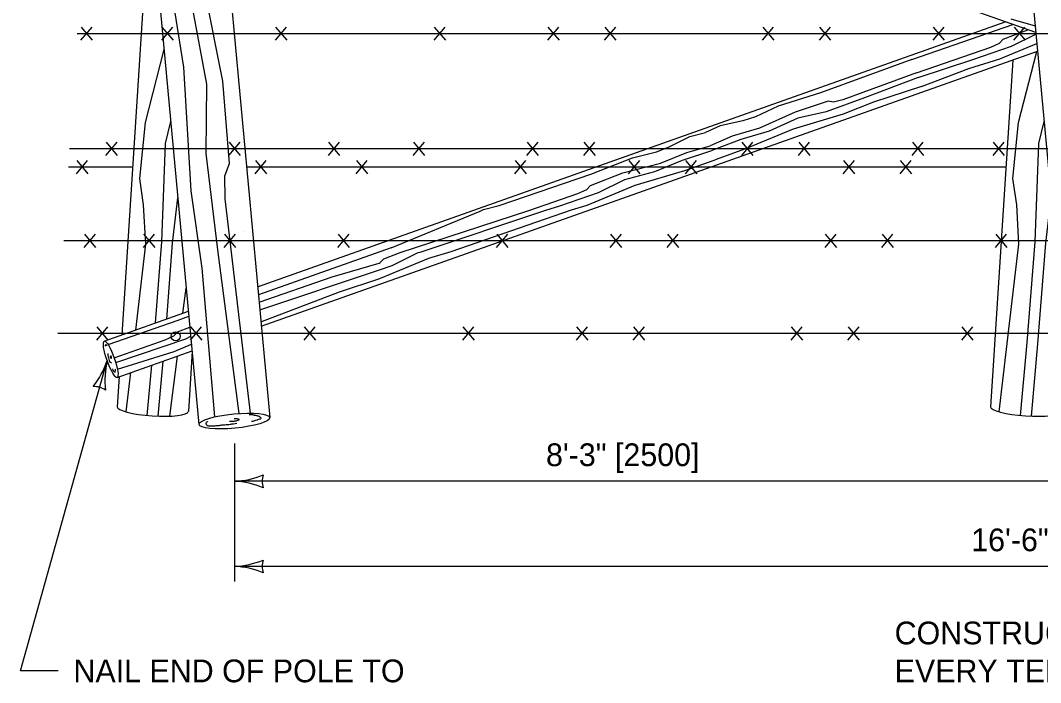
# Model space of a CAD drawing. Extents: x 49991.4 to 50021, y 49987.6 to 50011.4.
# Drawn here: x 50009.373 to 50012.065, y 49990.289 to 49992.035 of the extents above; entities that cross this region are included whole.
import ezdxf

# ---------------------------------------------------------------- set-up
doc = ezdxf.new("R2010")
doc.units = 0
for name, color, linetype in [('Level 1', 7, 'Continuous'), ('Level 2', 7, 'Continuous'), ('Level 3', 7, 'Continuous')]:
    doc.layers.add(name, color=color, linetype=linetype)

msp = doc.modelspace()

# ---------------------------------------------------------------- linework, layer by layer
at = {"layer": 'Level 1'}
for p, q in [((50009.7558, 49992.9922), (50009.6409, 49991.206)), ((50012.0526, 49992.0031), (50010.2289, 49992.649)), ((50009.9017, 49992.3783), (50010.0312, 49990.9877)), ((50009.7178, 49992.3281), (50009.8443, 49990.9698)), ((50012.0223, 49992.3281), (50012.1488, 49990.9698)), ((50009.9991, 49991.3328), (50011.9723, 49992.0316)), ((50011.987, 49992.0392), (50012.0509, 49992.0211)), ((50009.5224, 49992.001), (50010.3579, 49992.001)), ((50009.5327, 49991.9829), (50009.562, 49992.0176)), ((50009.5634, 49991.9829), (50009.534, 49992.0176)), ((50009.746, 49991.9829), (50009.7754, 49992.0176)), ((50009.7767, 49991.9829), (50009.7474, 49992.0176)), ((50010.046, 49991.9829), (50010.0754, 49992.0176)), ((50010.0767, 49991.9829), (50010.0474, 49992.0176)), ((50010.3579, 49992.001), (50012.6067, 49992.001)), ((50010.4648, 49991.9829), (50010.4942, 49992.0176)), ((50010.4955, 49991.9829), (50010.4662, 49992.0176)), ((50010.7648, 49991.9829), (50010.7942, 49992.0176)), ((50010.7955, 49991.9829), (50010.7662, 49992.0176)), ((50010.9148, 49991.9829), (50010.9442, 49992.0176)), ((50010.9455, 49991.9829), (50010.9162, 49992.0176)), ((50011.3315, 49991.9829), (50011.3608, 49992.0176)), ((50011.3622, 49991.9829), (50011.3328, 49992.0176)), ((50011.4815, 49991.9829), (50011.5108, 49992.0176)), ((50011.5122, 49991.9829), (50011.4828, 49992.0176)), ((50011.7815, 49991.9829), (50011.8108, 49992.0176)), ((50011.8122, 49991.9829), (50011.7828, 49992.0176)), ((50011.9948, 49991.9829), (50012.0242, 49992.0176)), ((50012.0255, 49991.9829), (50011.9962, 49992.0176)), ((50010.878, 49991.5364), (50012.0572, 49991.9539)), ((50011.9921, 49991.9309), (50011.9332, 49991.0165)), ((50009.5987, 49991.6795), (50009.6281, 49991.7142)), ((50009.6294, 49991.6795), (50009.6001, 49991.7142)), ((50009.9232, 49991.6795), (50009.9526, 49991.7142)), ((50009.9539, 49991.6795), (50009.9246, 49991.7142)), ((50010.1857, 49991.6795), (50010.2151, 49991.7142)), ((50010.2164, 49991.6795), (50010.1871, 49991.7142)), ((50010.4098, 49991.6795), (50010.4392, 49991.7142)), ((50010.4405, 49991.6795), (50010.4112, 49991.7142)), ((50010.7098, 49991.6795), (50010.7392, 49991.7142)), ((50010.7405, 49991.6795), (50010.7112, 49991.7142)), ((50010.8598, 49991.6795), (50010.8892, 49991.7142)), ((50010.8905, 49991.6795), (50010.8612, 49991.7142)), ((50011.2765, 49991.6795), (50011.3058, 49991.7142)), ((50011.3072, 49991.6795), (50011.2778, 49991.7142)), ((50011.4265, 49991.6795), (50011.4558, 49991.7142)), ((50011.4572, 49991.6795), (50011.4278, 49991.7142)), ((50011.7265, 49991.6795), (50011.7558, 49991.7142)), ((50011.7572, 49991.6795), (50011.7278, 49991.7142)), ((50011.9398, 49991.6795), (50011.9692, 49991.7142)), ((50011.9705, 49991.6795), (50011.9412, 49991.7142)), ((50009.5028, 49991.6976), (50010.3029, 49991.6976)), ((50010.3029, 49991.6976), (50012.5517, 49991.6976)), ((50009.4997, 49991.6491), (50009.6701, 49991.6491)), ((50009.5211, 49991.631), (50009.5504, 49991.6657)), ((50009.5518, 49991.631), (50009.5224, 49991.6657)), ((50009.9686, 49991.6491), (50011.9739, 49991.6491)), ((50009.9925, 49991.631), (50010.0219, 49991.6657)), ((50010.0232, 49991.631), (50009.9939, 49991.6657)), ((50010.2591, 49991.631), (50010.2885, 49991.6657)), ((50010.2898, 49991.631), (50010.2605, 49991.6657)), ((50010.6779, 49991.631), (50010.7073, 49991.6657)), ((50010.7086, 49991.631), (50010.6793, 49991.6657)), ((50010.9779, 49991.631), (50011.0073, 49991.6657)), ((50011.0086, 49991.631), (50010.9793, 49991.6657)), ((50011.1279, 49991.631), (50011.1573, 49991.6657)), ((50011.1586, 49991.631), (50011.1293, 49991.6657)), ((50011.5446, 49991.631), (50011.5739, 49991.6657)), ((50011.5753, 49991.631), (50011.5459, 49991.6657)), ((50011.6946, 49991.631), (50011.7239, 49991.6657)), ((50011.7253, 49991.631), (50011.6959, 49991.6657)), ((50010.0088, 49991.2286), (50010.878, 49991.5364)), ((50010.3512, 49991.4356), (50010.586, 49991.5321)), ((50010.3755, 49991.4235), (50010.7145, 49991.534)), ((50010.4284, 49991.4243), (50010.76, 49991.5347)), ((50010.51, 49991.4256), (50010.8277, 49991.5356)), ((50009.5416, 49991.4368), (50009.5709, 49991.4715)), ((50009.5723, 49991.4368), (50009.5429, 49991.4715)), ((50009.6977, 49991.4368), (50009.727, 49991.4715)), ((50009.7284, 49991.4368), (50009.699, 49991.4715)), ((50009.911, 49991.4368), (50009.9404, 49991.4715)), ((50009.9417, 49991.4368), (50009.9124, 49991.4715)), ((50009.9655, 49991.4793), (50009.9655, 49991.4793)), ((50010.211, 49991.4368), (50010.2404, 49991.4715)), ((50010.2417, 49991.4368), (50010.2124, 49991.4715)), ((50010.6298, 49991.4368), (50010.6592, 49991.4715)), ((50010.6605, 49991.4368), (50010.6312, 49991.4715)), ((50010.9298, 49991.4368), (50010.9592, 49991.4715)), ((50010.9605, 49991.4368), (50010.9312, 49991.4715)), ((50011.0798, 49991.4368), (50011.1092, 49991.4715)), ((50011.1105, 49991.4368), (50011.0812, 49991.4715)), ((50011.4965, 49991.4368), (50011.5258, 49991.4715)), ((50011.5272, 49991.4368), (50011.4978, 49991.4715)), ((50011.6465, 49991.4368), (50011.6758, 49991.4715)), ((50011.6772, 49991.4368), (50011.6478, 49991.4715)), ((50011.9465, 49991.4368), (50011.9758, 49991.4715)), ((50011.9772, 49991.4368), (50011.9478, 49991.4715)), ((50009.4872, 49991.4549), (50010.5229, 49991.4549)), ((50010.3512, 49991.4356), (50010.0011, 49991.3118)), ((50010.5229, 49991.4549), (50012.7717, 49991.4549)), ((50010.196, 49991.3591), (50010.3195, 49991.3951)), ((50010.0029, 49991.2919), (50010.196, 49991.3591)), ((50010.0048, 49991.2717), (50010.3211, 49991.3773)), ((50010.2151, 49991.3196), (50010.3213, 49991.3547)), ((50009.5943, 49991.1895), (50009.8165, 49991.2682)), ((50009.5743, 49991.1923), (50009.6036, 49991.227)), ((50009.605, 49991.1923), (50009.5756, 49991.227)), ((50009.8216, 49991.1923), (50009.851, 49991.227)), ((50009.8523, 49991.1923), (50009.823, 49991.227)), ((50010.1216, 49991.1923), (50010.151, 49991.227)), ((50010.1523, 49991.1923), (50010.123, 49991.227)), ((50010.5404, 49991.1923), (50010.5698, 49991.227)), ((50010.5711, 49991.1923), (50010.5418, 49991.227)), ((50010.8404, 49991.1923), (50010.8698, 49991.227)), ((50010.8711, 49991.1923), (50010.8418, 49991.227)), ((50010.9904, 49991.1923), (50011.0198, 49991.227)), ((50011.0211, 49991.1923), (50010.9918, 49991.227)), ((50011.4071, 49991.1923), (50011.4364, 49991.227)), ((50011.4378, 49991.1923), (50011.4084, 49991.227)), ((50011.5571, 49991.1923), (50011.5864, 49991.227)), ((50011.5878, 49991.1923), (50011.5584, 49991.227)), ((50011.8571, 49991.1923), (50011.8864, 49991.227)), ((50011.8878, 49991.1923), (50011.8584, 49991.227)), ((50009.4715, 49991.2105), (50010.4335, 49991.2105)), ((50010.4335, 49991.2105), (50012.6823, 49991.2105)), ((50009.6285, 49991.0939), (50009.8262, 49991.1639)), ((50009.8263, 49991.1628), (50009.8163, 49991.0042)), ((50009.6338, 49991.0958), (50009.6287, 49991.0165))]:
    msp.add_line(p, q, dxfattribs=at)
for points in [[(50009.9505, 49990.9988), (50009.8938, 49991.4307), (50009.8632, 49991.6848), (50009.8653, 49991.8677), (50009.8285, 49992.0604), (50009.8176, 49992.2455), (50009.8033, 49992.3553)], [(50009.9799, 49990.9996), (50009.913, 49991.5649), (50009.9125, 49991.6258), (50009.9245, 49991.6576), (50009.9071, 49991.8755), (50009.8594, 49992.1145), (50009.8493, 49992.2929), (50009.8373, 49992.3594)], [(50009.8863, 49990.9899), (50009.853, 49991.3822), (50009.8235, 49991.5856), (50009.8047, 49991.9121), (50009.7533, 49992.2317), (50009.7412, 49992.3433)], [(50011.7257, 49991.9327), (50011.9925, 49992.0244)], [(50011.7382, 49991.8973), (50011.9339, 49991.9645), (50011.9572, 49991.9754), (50011.967, 49991.9857), (50012.0314, 49992.0106)], [(50011.7425, 49991.8852), (50011.8866, 49991.9327), (50011.9885, 49991.9675), (50012.0529, 49991.9993)], [(50011.7511, 49991.8609), (50011.8756, 49991.9084), (50011.9582, 49991.9343), (50012.0553, 49991.9743)], [(50009.6772, 49991.2188), (50009.7037, 49991.4452), (50009.6982, 49991.5488), (50009.6879, 49991.6186), (50009.703, 49991.7661), (50009.7522, 49991.9589)], [(50011.9564, 49991.0028), (50011.9855, 49991.2512), (50012.0083, 49991.4452), (50012.0028, 49991.5488), (50011.9925, 49991.6186), (50012.0075, 49991.7661), (50012.0553, 49991.9533)], [(50011.7257, 49991.9327), (50011.4846, 49991.8448), (50011.3725, 49991.8091), (50011.3132, 49991.7814), (50011.2794, 49991.7708), (50011.2193, 49991.7577), (50011.1809, 49991.7398)], [(50011.7382, 49991.8973), (50011.5438, 49991.8263), (50011.519, 49991.8202), (50011.5048, 49991.822), (50011.4173, 49991.7938), (50011.3239, 49991.7511), (50011.2518, 49991.7297), (50011.1934, 49991.7043)], [(50011.7425, 49991.8852), (50011.6007, 49991.8314), (50011.4995, 49991.7943), (50011.4245, 49991.7775), (50011.3491, 49991.7437), (50011.2743, 49991.7213), (50011.1977, 49991.6922)], [(50011.7511, 49991.8609), (50011.6245, 49991.8194), (50011.544, 49991.7877), (50011.4121, 49991.7483), (50011.2862, 49991.6964), (50011.2063, 49991.668)], [(50009.7295, 49991.2374), (50009.7464, 49991.451), (50009.7563, 49991.711), (50009.7699, 49991.7691)], [(50012.0124, 49990.9933), (50012.03, 49991.1858), (50012.0509, 49991.451), (50012.0608, 49991.711), (50012.0744, 49991.7691)], [(50010.6361, 49991.5469), (50010.8786, 49991.6302), (50010.9882, 49991.6731), (50011.0518, 49991.6888), (50011.0848, 49991.7019), (50011.1396, 49991.7295), (50011.1809, 49991.7398)], [(50010.7145, 49991.534), (50010.8444, 49991.5786), (50010.8675, 49991.5895), (50010.8774, 49991.5999), (50010.9632, 49991.633), (50011.0625, 49991.6586), (50011.1321, 49991.6873), (50011.1934, 49991.7043)], [(50010.76, 49991.5347), (50010.797, 49991.5468), (50010.8988, 49991.5815), (50010.9679, 49991.6158), (50011.0477, 49991.6369), (50011.1199, 49991.6666), (50011.1977, 49991.6922)], [(50010.8277, 49991.5356), (50010.8685, 49991.5484), (50010.9957, 49991.6009), (50011.1263, 49991.6398), (50011.2063, 49991.668)], [(50009.759, 49991.2478), (50009.7748, 49991.4481), (50009.7886, 49991.5678)], [(50012.041, 49990.9915), (50012.0584, 49991.1828), (50012.0794, 49991.4481), (50012.0931, 49991.5678)], [(50010.586, 49991.5321), (50010.5949, 49991.5366), (50010.6361, 49991.5469)], [(50010.3195, 49991.3951), (50010.3227, 49991.3966), (50010.3325, 49991.4069), (50010.3755, 49991.4235)], [(50010.3211, 49991.3773), (50010.3541, 49991.3886), (50010.423, 49991.4229), (50010.4284, 49991.4243)], [(50010.3213, 49991.3547), (50010.3237, 49991.3554), (50010.4509, 49991.408), (50010.51, 49991.4256)], [(50009.8016, 49991.2629), (50009.8108, 49991.3293)], [(50010.0077, 49991.2405), (50010.2151, 49991.3196)], [(50009.6042, 49991.1805), (50009.7891, 49991.2444), (50009.8177, 49991.2556)], [(50009.6203, 49991.1458), (50009.7547, 49991.1928), (50009.7778, 49991.2037), (50009.7877, 49991.2139), (50009.8204, 49991.2266)], [(50009.6246, 49991.1328), (50009.8093, 49991.1957), (50009.8227, 49991.2023)], [(50009.629, 49991.1154), (50009.7788, 49991.1625), (50009.8246, 49991.1814)], [(50009.6013, 49991.1399), (50009.6013, 49991.1399)], [(50009.7365, 49990.9915), (50009.7497, 49991.1368)], [(50009.7673, 49990.9916), (50009.7874, 49991.1502)], [(50009.7079, 49990.9933), (50009.72, 49991.1263)], [(50009.6518, 49991.0028), (50009.664, 49991.1065)]]:
    msp.add_lwpolyline(points, dxfattribs=at)
msp.add_circle((50009.7826, 49991.2022), 0.012, dxfattribs=at)
for centre, major_axis, ratio in [((50009.6113, 49991.1416), (-0.0169, 0.0479), 0.196346), ((50009.9376, 49990.9788), (0.0932, 0.0089), 0.201992)]:
    msp.add_ellipse(centre, major_axis=major_axis, ratio=ratio, dxfattribs=at)
for centre in [(50009.7224, 49991.0104), (50012.0269, 49991.0104)]:
    msp.add_ellipse(centre, major_axis=(-0.0937, 0.0061), ratio=0.194104, start_param=0.000064, end_param=3.132664, dxfattribs=at)
for points in [[(50009.6016, 49991.1771), (50009.6006, 49991.1791), (50009.5978, 49991.1796), (50009.5972, 49991.179), (50009.5966, 49991.176)], [(50009.6034, 49991.1567), (50009.6035, 49991.1519), (50009.6054, 49991.1451), (50009.6104, 49991.1337), (50009.6133, 49991.1324)], [(50009.6102, 49991.1496), (50009.6125, 49991.1441), (50009.6137, 49991.1452), (50009.613, 49991.1474), (50009.6125, 49991.1512)], [(50009.6157, 49991.1161), (50009.6184, 49991.1107), (50009.6209, 49991.1083), (50009.6231, 49991.108), (50009.6233, 49991.1088), (50009.6242, 49991.1155)], [(50009.868, 49990.9774), (50009.8657, 49990.9764), (50009.8631, 49990.9743), (50009.8623, 49990.9721), (50009.8636, 49990.97), (50009.8649, 49990.9679), (50009.8673, 49990.9669), (50009.8706, 49990.966), (50009.8764, 49990.9658), (50009.8846, 49990.9658), (50009.8895, 49990.9666), (50009.895, 49990.9671), (50009.9044, 49990.9686), (50009.9127, 49990.9692), (50009.9194, 49990.9697), (50009.9267, 49990.9703), (50009.9357, 49990.9718), (50009.9439, 49990.9731)], [(50009.9369, 49990.9851), (50009.94, 49990.9855), (50009.9442, 49990.9851), (50009.9464, 49990.9848), (50009.9492, 49990.9833), (50009.9494, 49990.9816), (50009.9467, 49990.9798), (50009.9424, 49990.9787), (50009.9376, 49990.978), (50009.934, 49990.9776), (50009.9285, 49990.9774), (50009.9258, 49990.9774), (50009.9249, 49990.9774)], [(50009.9763, 49990.9957), (50009.9809, 49990.9957), (50009.9854, 49990.9957), (50009.9886, 49990.995), (50009.9916, 49990.9942), (50009.9963, 49990.9936), (50009.9987, 49990.9927), (50010.0024, 49990.9915), (50010.0038, 49990.9907), (50010.005, 49990.9895), (50010.0065, 49990.9881), (50010.0074, 49990.9859), (50010.0068, 49990.9848), (50010.0042, 49990.9833), (50009.9987, 49990.9816), (50009.9968, 49990.981), (50009.9901, 49990.979), (50009.9877, 49990.9785), (50009.9846, 49990.9774), (50009.9832, 49990.9774)]]:
    msp.add_spline(points, degree=3, dxfattribs=at)
at = {"layer": 'Level 3'}
for p, q in [((50009.9376, 49990.9198), (50009.9376, 49990.5554)), ((50012.2421, 49990.8198), (50009.9376, 49990.8198)), ((50014.5466, 49990.5954), (50009.9376, 49990.5954))]:
    msp.add_line(p, q, dxfattribs=at)
msp.add_lwpolyline([(50009.473, 49990.3198), (50009.373, 49990.3198), (50009.6019, 49991.1383)], dxfattribs=at)
for centre, radius, start, end in [((50009.3904, 49991.2069), 0.2223, 321.8311, 342.0146), ((50009.8291, 49991.0867), 0.233, 167.2024, 186.4522), ((50009.5673, 49991.0148), 0.0548, 56.5139, 92.2362), ((50009.9261, 49991.0525), 0.233, 272.8273, 292.0772), ((50009.9284, 49990.5976), 0.2223, 67.456, 87.6395), ((50010.0658, 49990.8198), 0.0548, 162.1388, 197.8612), ((50009.9261, 49990.8281), 0.233, 272.8273, 292.0772), ((50010.0658, 49990.5954), 0.0548, 162.1388, 197.8612), ((50009.9284, 49990.3733), 0.2223, 67.456, 87.6395)]:
    msp.add_arc(centre, radius, start, end, dxfattribs=at)

# ---------------------------------------------------------------- texts
at = {"layer": 'Level 2'}
for s, p in [('8\'-3" [2500]', (50010.7601, 49990.8598)), ('16\'-6" [5000]', (50011.8823, 49990.6354))]:
    msp.add_text(s, height=0.06, rotation=0, dxfattribs=at).set_placement(p)
for s, p in [('CONSTRUCT BRACE', (50011.6802, 49990.3898)), ('NAIL END OF POLE TO', (50009.513, 49990.2898)), ('EVERY TEN POLE LENGTHS ', (50011.6802, 49990.2898))]:
    msp.add_text(s, height=0.06, dxfattribs=at).set_placement(p)

doc.saveas('drawing.dxf')
